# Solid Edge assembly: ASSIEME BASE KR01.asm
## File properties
Author: f_grande
Template: Normal.asm
Last saved by: f_grande
Revision: 35
Application: Solid Edge
Tipo di contenuto documento: 1
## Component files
ASSIEME MOTORE.asm
dad-M5.par
TCE M5x25.par
ALBERO_25X1100.par
VITE RICIRCOLO_1120.par
TSPE M5x35.par
BUSSOLA-ZAM-M8x15.par
TRUC_5x20_TSPI.par
SUPPORTO ALB_25.par
TCE M5x15.par
CHIOCCIOLA.par
Rosetta-D8.par
SUPPORTO CUSC 6200.par
TCE M8x35.par
6200.asm
7201_BEGAP.asm
ALLUMINIO_1012.par
Fronte.par
PIANO LAVORO.par
BOCCOLA M12.par
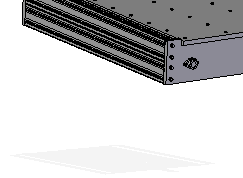
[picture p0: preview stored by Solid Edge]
